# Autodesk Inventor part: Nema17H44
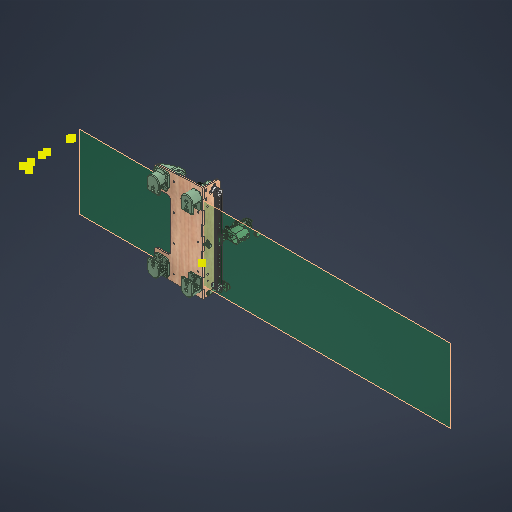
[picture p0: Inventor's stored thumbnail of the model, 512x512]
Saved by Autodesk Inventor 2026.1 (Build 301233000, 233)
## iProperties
Created: 2025-11
Part Number: Nema17H44
Material: Steel
Document SubType Name: Modeling
Designer: Yury Melnikov
Density: 7.85 g/cm^3
Appearance: Резина — зеленая
Mass: 34859.8 g
Surface Area: 7325.72 cm^2
Volume: 4440.74 cm^3
Sending System: Autodesk Translation Framework v14.17.0.0
Preprocessor: ST-DEVELOPER v20.1
Title: m2_20.step
## Parameters: d0 = 504 deg, d1 = 12.56644 mm, d2 = 201.062 mm, d3 = 16 mm, d4 = 72 deg, d5 = 16 mm, d8 = 0, d11 = 201 mm, d14 = 16 mm, d15 = 0, d16 = 16 mm, d18 = 30.5 mm, d19 = 30.5 mm, d22 = 30.5 mm, d25 = 30.5 mm, d28 = 3.3 mm, d29 = 4.8 mm, d30 = 4.8 mm, d31 = 4.8 mm, d32 = 4.8 mm, d33 = 16 mm, d37 = 2.348 mm, d38 = 2.348 mm, d40 = 0, d42 = 8.1 mm, d43 = 8.1 mm, d44 = 5.9 mm, d45 = 5.9 mm, d47 = 0, d52 = 8 mm, d53 = 4 mm, d55 = 5 mm, d56 = 11 mm, d57 = 12.2 mm, d58 = 6.1 mm, d60 = 36 mm, d61 = 45 mm, d63 = 8.1 mm, d64 = 5 mm, d65 = 3 mm, d66 = 5.7 mm, d67 = 4 mm, d68 = 0, d70 = 3 mm, d72 = 213.75 mm, d73 = 0, d74 = 1 mm, d75 = 2 mm, d76 = 45 deg, d77 = 22 mm, d78 = 1 mm, d80 = 16 mm, d81 = 8 mm, d82 = 12 mm, d84 = 213.75 mm, d85 = 0, d86 = 2 mm, d92 = 360 deg, d94 = 4 mm, d95 = 5 mm, d96 = 0, d97 = 0.7 mm, d98 = 2 mm, d99 = 45 deg, d100 = 31.1 mm, d101 = 31.1 mm, d102 = 42 mm, d103 = 44 mm, d106 = 31.1 mm, d109 = 31.1 mm, d112 = 3.3 mm, d113 = 4.8 mm, d114 = 4.8 mm, d115 = 4.8 mm, d116 = 4.8 mm, d117 = 4.8 mm, d118 = 4.8 mm, d119 = 4.8 mm, d120 = 4.8 mm, d121 = 4 mm, d122 = 0, d123 = 5 mm, d124 = 4 mm, d125 = 0, d126 = 2 mm, d127 = 2 mm, d128 = 45 deg, d129 = 3 mm, d130 = 3 mm, d131 = 2 mm, d132 = 2 mm, d133 = 24 mm, d134 = 2.8 mm, d135 = 2.8 mm, d138 = 6 mm, d139 = 6 mm, d140 = 4 mm, d141 = 0, d145 = 1 mm, d146 = 2 mm, d147 = 45 deg, d149 = 4 mm, d150 = 0, d154 = 1 mm, d155 = 2 mm, d156 = 45 deg, d157 = 105 mm, d158 = 45 mm, d160 = 0, d161 = 3 mm, d162 = 2 mm, d163 = 45 deg, d165 = 9.25 mm, d166 = 18 mm, d168 = 31 mm, d169 = 44 mm, d171 = 16 mm, d172 = 8 mm, d173 = 14 mm, d176 = 0, d179 = 16 mm, d180 = 0, d182 = 2 mm, d183 = 8 mm, d187 = 3 mm, d188 = 22.4 mm, d190 = 3 mm, d191 = 3 mm, d192 = 4 mm, d193 = 16 mm, d194 = 16 mm, d195 = 5 mm, d197 = 3 mm, d198 = 2 mm, d199 = 6 mm, d200 = 90 deg, d201 = 26 mm, d202 = 16 mm, d203 = 2 mm, d204 = 6 mm, d205 = 247 mm, d206 = 90 deg, d207 = 9.1 mm, d208 = 24 mm, d209 = 3 mm, d210 = 31.1 mm, d213 = 31.1 mm, d216 = 31.1 mm, d219 = 43 mm, d220 = 43 mm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
